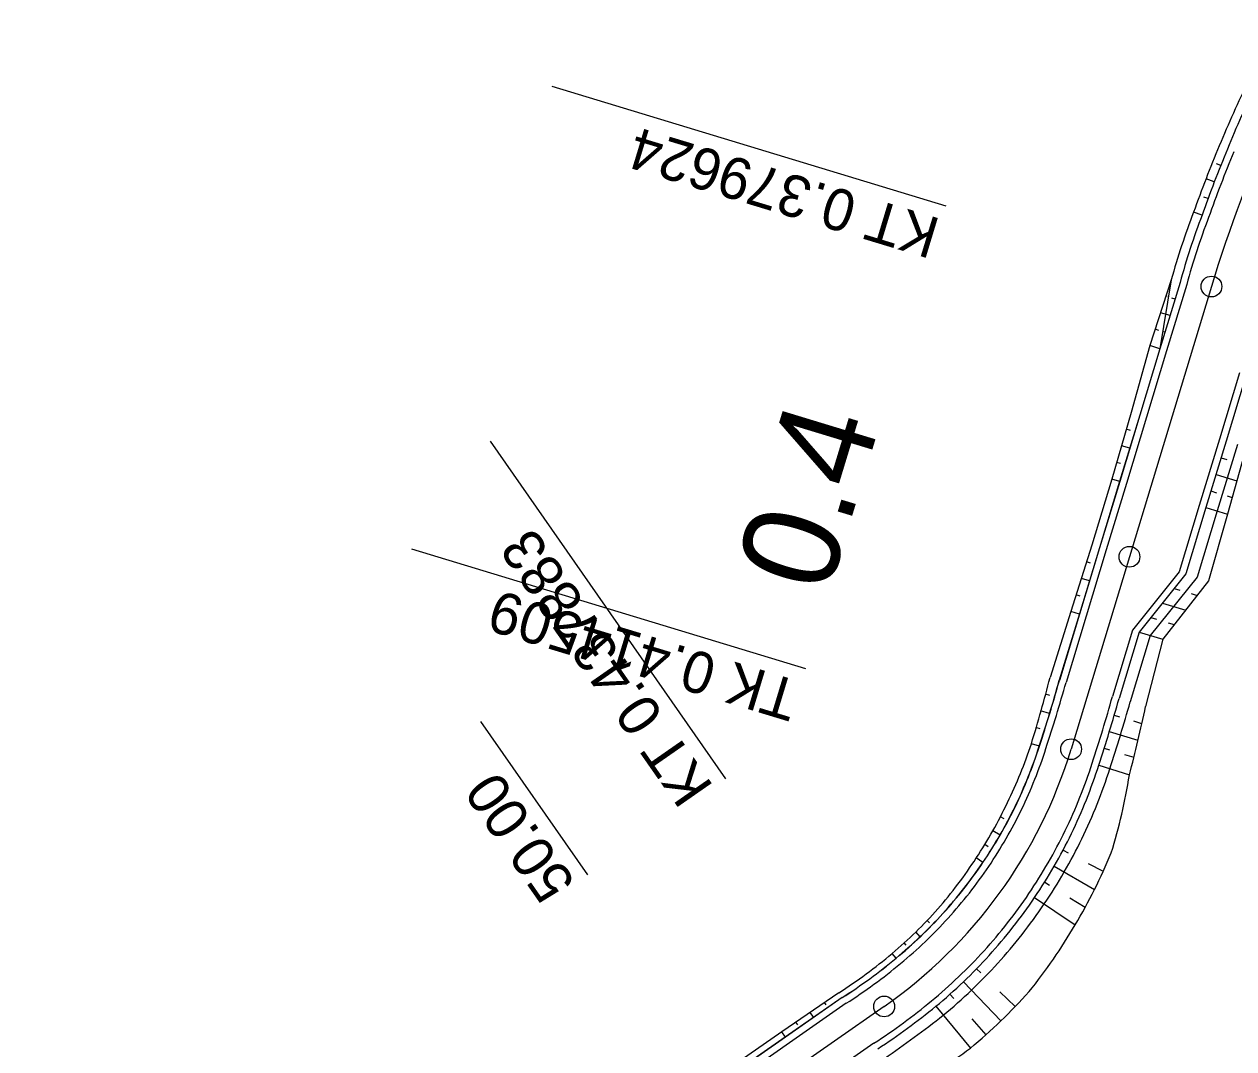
# Model space of a CAD drawing. Extents: x -481656 to -478728, y -1113199 to -1110710.
# Drawn here: x -479662.7 to -479575.4, y -1112765 to -1112691.1 of the extents above; entities that cross this region are included whole.
import ezdxf

# ---------------------------------------------------------------- set-up
doc = ezdxf.new("R2010")
doc.units = 0
for name, color, linetype in [('C1_HATCH_SLOPE_L', 7, 'Continuous'), ('C1_HATCH_SLOPE_R', 7, 'Continuous'), ('C1_HECTOMETRY', 7, 'Continuous'), ('C1_HLBODY', 7, 'Continuous'), ('C1_HRANA_TELESO', 7, 'Continuous'), ('C1_KORUNA', 7, 'Continuous'), ('C1_OSA', 7, 'Continuous'), ('C1_PRIKOP', 7, 'Continuous'), ('C1_STANICENI', 7, 'Continuous'), ('C1_VOZOVKA', 7, 'Continuous'), ('C1_ZPEVKRAJ', 7, 'Continuous')]:
    doc.layers.add(name, color=color, linetype=linetype)

msp = doc.modelspace()

# ---------------------------------------------------------------- linework, layer by layer
at = {"layer": 'C1_HATCH_SLOPE_L'}
for p, q in [((-479576.368, -1112722.337), (-479575.961, -1112722.46)), ((-479576.731, -1112723.533), (-479575.23, -1112723.988)), ((-479577.094, -1112724.729), (-479576.687, -1112724.852)), ((-479575.926, -1112725.084), (-479575.571, -1112725.191)), ((-479577.456, -1112725.925), (-479575.912, -1112726.394)), ((-479579.749, -1112731.761), (-479579.344, -1112731.884)), ((-479580.59, -1112732.812), (-479578.92, -1112733.319)), ((-479578.518, -1112732.134), (-479578.097, -1112732.262)), ((-479581.432, -1112733.863), (-479581.029, -1112733.985)), ((-479580.185, -1112734.241), (-479579.743, -1112734.375)), ((-479582.273, -1112734.914), (-479580.567, -1112735.432)), ((-479584.087, -1112740.895), (-479583.686, -1112741.016)), ((-479582.691, -1112741.318), (-479582.097, -1112741.499)), ((-479584.45, -1112742.092), (-479582.382, -1112742.719)), ((-479584.812, -1112743.288), (-479584.412, -1112743.41)), ((-479583.34, -1112743.734), (-479582.668, -1112743.938)), ((-479585.188, -1112744.513), (-479582.976, -1112745.218)), ((-479587.761, -1112750.637), (-479587.391, -1112750.833)), ((-479588.405, -1112751.802), (-479585.493, -1112753.479)), ((-479585.944, -1112751.6), (-479584.868, -1112752.17)), ((-479589.09, -1112752.942), (-479588.734, -1112753.164)), ((-479589.815, -1112754.057), (-479586.887, -1112756.035)), ((-479587.273, -1112754.078), (-479586.167, -1112754.769)), ((-479594.01, -1112759.208), (-479593.71, -1112759.5)), ((-479594.955, -1112760.144), (-479592.261, -1112762.966)), ((-479592.316, -1112760.86), (-479591.221, -1112761.928)), ((-479595.934, -1112761.045), (-479595.656, -1112761.358)), ((-479596.944, -1112761.911), (-479594.449, -1112764.928)), ((-479594.357, -1112762.818), (-479593.337, -1112763.966))]:
    msp.add_line(p, q, dxfattribs=at)
at = {"layer": 'C1_HATCH_SLOPE_R'}
for p, q in [((-479576.979, -1112701.01), (-479576.979, -1112701.01)), ((-479576.389, -1112701.244), (-479576.684, -1112701.127)), ((-479576.853, -1112702.435), (-479577.45, -1112702.206)), ((-479577.907, -1112703.409), (-479577.907, -1112703.409)), ((-479577.303, -1112703.632), (-479577.605, -1112703.52)), ((-479577.737, -1112704.833), (-479578.349, -1112704.617)), ((-479580.255, -1112710.708), (-479580.347, -1112710.68)), ((-479579.686, -1112710.881), (-479579.924, -1112710.808)), ((-479580.049, -1112712.077), (-479580.736, -1112711.868)), ((-479580.852, -1112713.14), (-479581.126, -1112713.056)), ((-479580.411, -1112713.273), (-479580.494, -1112713.248)), ((-479580.774, -1112714.469), (-479581.516, -1112714.244)), ((-479582.9, -1112720.356), (-479583.203, -1112720.264)), ((-479582.588, -1112720.45), (-479582.593, -1112720.448)), ((-479582.951, -1112721.646), (-479583.551, -1112721.464)), ((-479583.611, -1112722.752), (-479583.899, -1112722.665)), ((-479583.314, -1112722.843), (-479583.318, -1112722.842)), ((-479583.677, -1112724.039), (-479584.246, -1112723.866)), ((-479585.786, -1112729.93), (-479586.072, -1112729.844)), ((-479585.491, -1112730.02), (-479585.496, -1112730.018)), ((-479585.853, -1112731.216), (-479586.447, -1112731.036)), ((-479586.524, -1112732.318), (-479586.823, -1112732.228)), ((-479586.216, -1112732.412), (-479586.221, -1112732.41)), ((-479586.579, -1112733.608), (-479587.198, -1112733.421)), ((-479588.723, -1112739.489), (-479589.043, -1112739.392)), ((-479588.393, -1112739.589), (-479588.398, -1112739.588)), ((-479588.756, -1112740.785), (-479589.382, -1112740.596)), ((-479589.424, -1112741.889), (-479589.721, -1112741.799)), ((-479589.119, -1112741.982), (-479589.124, -1112741.98)), ((-479589.475, -1112743.147), (-479590.051, -1112742.963)), ((-479592.017, -1112748.383), (-479592.287, -1112748.24)), ((-479591.738, -1112748.531), (-479591.742, -1112748.528)), ((-479592.304, -1112749.555), (-479592.832, -1112749.25)), ((-479593.164, -1112750.396), (-479593.413, -1112750.241)), ((-479593.543, -1112751.538), (-479594.029, -1112751.21)), ((-479592.906, -1112750.557), (-479592.91, -1112750.554)), ((-479597.408, -1112755.894), (-479597.577, -1112755.729)), ((-479597.232, -1112756.066), (-479597.236, -1112756.062)), ((-479599.078, -1112757.507), (-479599.227, -1112757.34)), ((-479598.063, -1112756.889), (-479598.387, -1112756.549)), ((-479599.811, -1112758.443), (-479600.094, -1112758.101)), ((-479598.923, -1112757.682), (-479598.926, -1112757.678)), ((-479604.849, -1112761.816), (-479604.971, -1112761.641)), ((-479605.747, -1112762.713), (-479606.002, -1112762.347)), ((-479604.721, -1112761.999), (-479604.724, -1112761.995)), ((-479606.906, -1112763.236), (-479607.034, -1112763.052)), ((-479606.773, -1112763.428), (-479606.776, -1112763.424)), ((-479607.798, -1112764.142), (-479608.066, -1112763.758))]:
    msp.add_line(p, q, dxfattribs=at)
at = {"layer": 'C1_HECTOMETRY'}
msp.add_circle((-479582.975, -1112729.477), 0.75, dxfattribs=at)
at = {"layer": 'C1_HLBODY'}
for p, q in [((-479596.2, -1112704.173), (-479624.621, -1112695.553)), ((-479612.105, -1112745.51), (-479629.082, -1112721.141)), ((-479606.325, -1112737.556), (-479634.746, -1112728.936))]:
    msp.add_line(p, q, dxfattribs=at)
for centre in [(-479577.061, -1112709.978), (-479587.186, -1112743.361), (-479600.673, -1112761.92)]:
    msp.add_circle(centre, 0.75, dxfattribs=at)
at = {"layer": 'C1_HRANA_TELESO'}
for p, q in [((-479579.957, -1112709.492), (-479581.516, -1112714.244)), ((-479581.516, -1112714.244), (-479582.856, -1112719.063)), ((-479582.856, -1112719.063), (-479584.246, -1112723.866)), ((-479574.548, -1112721.583), (-479575.912, -1112726.394)), ((-479584.246, -1112723.866), (-479585.696, -1112728.651)), ((-479575.912, -1112726.394), (-479577.274, -1112731.206)), ((-479585.696, -1112728.651), (-479587.198, -1112733.421)), ((-479577.274, -1112731.206), (-479580.567, -1112735.432)), ((-479587.198, -1112733.421), (-479588.703, -1112738.189)), ((-479580.567, -1112735.432), (-479581.811, -1112740.279)), ((-479603.939, -1112760.935), (-479608.066, -1112763.758)), ((-479608.066, -1112763.758), (-479612.175, -1112766.607))]:
    msp.add_line(p, q, dxfattribs=at)
for centre, radius, start, end in [((-479481.554, -1112739.428), 102.869, 154.48923, 157.35405), ((-479481.495, -1112739.339), 102.889, 157.41238, 160.27719), ((-479530.354, -1112723.151), 51.449, 158.88479, 164.60438), ((-479682.155, -1112714.38), 96.436, 342.75896, 345.70668), ((-479697.913, -1112715.507), 118.715, 345.50664, 347.95577), ((-479620.605, -1112733.017), 32.131, 333.7838, 341.96907), ((-479622.486, -1112738.943), 40.005, 342.69717, 350.97564), ((-479620.843, -1112733.489), 32.141, 326.54035, 334.72589), ((-479621.063, -1112733.701), 32.209, 318.8842, 327.07087), ((-479621.82, -1112735.325), 40.61, 329.33852, 337.53802), ((-479620.942, -1112733.456), 32.28, 310.22869, 318.41433), ((-479622.159, -1112735.21), 40.961, 321.24111, 329.44137), ((-479625.925, -1112727.085), 40.364, 303.00424, 309.78883), ((-479620.807, -1112733.325), 41.152, 309.82966, 318.01484), ((-479632.039, -1112713.382), 63.796, 301.15571, 306.10154)]:
    msp.add_arc(centre, radius, start, end, dxfattribs=at)
at = {"layer": 'C1_KORUNA'}
for p, q in [((-479579.323, -1112709.684), (-479580.774, -1112714.469)), ((-479580.774, -1112714.469), (-479582.225, -1112719.254)), ((-479574.554, -1112716.356), (-479576.005, -1112721.141)), ((-479582.225, -1112719.254), (-479583.677, -1112724.039)), ((-479576.005, -1112721.141), (-479577.456, -1112725.925)), ((-479583.677, -1112724.039), (-479585.128, -1112728.824)), ((-479577.456, -1112725.925), (-479578.908, -1112730.71)), ((-479585.128, -1112728.824), (-479586.579, -1112733.608)), ((-479578.908, -1112730.71), (-479582.273, -1112734.914)), ((-479586.579, -1112733.608), (-479588.03, -1112738.393)), ((-479582.273, -1112734.914), (-479583.724, -1112739.699)), ((-479603.696, -1112761.284), (-479607.798, -1112764.142)), ((-479607.798, -1112764.142), (-479611.901, -1112767.001))]:
    msp.add_line(p, q, dxfattribs=at)
for centre, radius, start, end in [((-479481.366, -1112739.002), 102.25, 154.74832, 157.61311), ((-479481.366, -1112739.002), 102.25, 157.61311, 160.4779), ((-479529.996, -1112723.122), 51.125, 159.03921, 164.76111), ((-479682.725, -1112712.201), 98.25, 341.64128, 344.53899), ((-479691.345, -1112709.601), 111.75, 341.79558, 344.37554), ((-479620.679, -1112733.202), 32.75, 334.13833, 342.32344), ((-479620.679, -1112733.202), 37.25, 334.13833, 342.32344), ((-479620.679, -1112733.202), 32.75, 325.95321, 334.13833), ((-479620.679, -1112733.202), 37.25, 325.95322, 334.13833), ((-479620.679, -1112733.202), 32.75, 317.7681, 325.95321), ((-479620.679, -1112733.202), 37.25, 317.76811, 325.95322), ((-479620.679, -1112733.202), 32.75, 309.58299, 317.7681), ((-479620.679, -1112733.202), 37.25, 309.583, 317.76811), ((-479626.364, -1112726.22), 41.754, 302.88139, 309.48942), ((-479627.852, -1112724.154), 48.794, 303.21491, 309.30428)]:
    msp.add_arc(centre, radius, start, end, dxfattribs=at)
at = {"layer": 'C1_OSA'}
for p, q in [((-479577.061, -1112709.978), (-479587.186, -1112743.361)), ((-479600.673, -1112761.92), (-479662.716, -1112805.144))]:
    msp.add_line(p, q, dxfattribs=at)
for centre, radius, start, end in [((-479481.366, -1112739.002), 100, 147.85753, 163.12732), ((-479620.679, -1112733.202), 35, 304.86324, 343.12729)]:
    msp.add_arc(centre, radius, start, end, dxfattribs=at)
at = {"layer": 'C1_PRIKOP'}
for p, q in [((-479579.957, -1112709.492), (-479580.784, -1112714.466)), ((-479580.784, -1112714.466), (-479582.235, -1112719.251)), ((-479582.235, -1112719.251), (-479583.686, -1112724.036)), ((-479575.191, -1112721.387), (-479576.642, -1112726.172)), ((-479583.686, -1112724.036), (-479585.137, -1112728.821)), ((-479576.642, -1112726.172), (-479578.094, -1112730.957)), ((-479585.137, -1112728.821), (-479586.589, -1112733.605)), ((-479578.094, -1112730.957), (-479581.471, -1112735.157)), ((-479586.589, -1112733.605), (-479588.04, -1112738.39)), ((-479581.471, -1112735.157), (-479582.922, -1112739.942)), ((-479603.701, -1112761.276), (-479607.804, -1112764.134)), ((-479607.804, -1112764.134), (-479611.907, -1112766.992))]:
    msp.add_line(p, q, dxfattribs=at)
for centre, radius, start, end in [((-479682.706, -1112712.207), 98.22, 341.64089, 344.5394), ((-479692.949, -1112709.117), 114.263, 341.82016, 344.34927), ((-479620.679, -1112733.202), 32.74, 334.13833, 342.32344), ((-479620.679, -1112733.202), 38.088, 334.13834, 342.32345), ((-479620.679, -1112733.202), 32.74, 325.95321, 334.13833), ((-479620.679, -1112733.202), 38.088, 325.95323, 334.13834), ((-479620.679, -1112733.202), 32.74, 317.7681, 325.95321), ((-479620.679, -1112733.202), 38.088, 317.76811, 325.95323), ((-479620.679, -1112733.202), 32.74, 309.58299, 317.7681), ((-479623.26, -1112730.462), 36.497, 302.40532, 309.96514), ((-479620.679, -1112733.202), 38.088, 309.583, 317.76811), ((-479653.686, -1112688.945), 93.27, 304.65876, 307.88574)]:
    msp.add_arc(centre, radius, start, end, dxfattribs=at)
at = {"layer": 'C1_STANICENI'}
msp.add_line((-479622.047, -1112752.436), (-479629.764, -1112741.359), dxfattribs=at)
at = {"layer": 'C1_VOZOVKA'}
for p, q in [((-479578.844, -1112709.83), (-479580.296, -1112714.614)), ((-479580.296, -1112714.614), (-479581.747, -1112719.399)), ((-479575.032, -1112716.211), (-479576.484, -1112720.995)), ((-479581.747, -1112719.399), (-479583.198, -1112724.184)), ((-479576.484, -1112720.995), (-479577.935, -1112725.78)), ((-479583.198, -1112724.184), (-479584.649, -1112728.969)), ((-479577.935, -1112725.78), (-479579.386, -1112730.565)), ((-479584.649, -1112728.969), (-479586.101, -1112733.753)), ((-479579.386, -1112730.565), (-479582.751, -1112734.769)), ((-479586.101, -1112733.753), (-479587.552, -1112738.538)), ((-479582.751, -1112734.769), (-479584.203, -1112739.554)), ((-479603.41, -1112761.695), (-479607.512, -1112764.553)), ((-479607.512, -1112764.553), (-479611.615, -1112767.411)), ((-479601.409, -1112764.566), (-479605.512, -1112767.425))]:
    msp.add_line(p, q, dxfattribs=at)
for centre, radius, start, end in [((-479481.366, -1112739.002), 101.75, 157.61311, 160.4779), ((-479529.758, -1112723.201), 50.875, 159.03862, 164.76259), ((-479683.683, -1112711.912), 99.75, 341.66054, 344.5187), ((-479690.387, -1112709.89), 110.25, 341.78035, 344.39177), ((-479620.679, -1112733.202), 33.25, 334.13833, 342.32344), ((-479620.679, -1112733.202), 36.75, 334.13833, 342.32344), ((-479620.679, -1112733.202), 33.25, 325.95321, 334.13833), ((-479620.679, -1112733.202), 36.75, 325.95322, 334.13833), ((-479620.679, -1112733.202), 33.25, 317.7681, 325.95321), ((-479620.679, -1112733.202), 36.75, 317.76811, 325.95322), ((-479620.679, -1112733.202), 33.25, 309.58299, 317.7681), ((-479620.679, -1112733.202), 36.75, 309.583, 317.76811), ((-479625.5, -1112727.396), 40.796, 302.78358, 309.60484), ((-479623.669, -1112729.862), 41.229, 302.67653, 309.82724)]:
    msp.add_arc(centre, radius, start, end, dxfattribs=at)
at = {"layer": 'C1_ZPEVKRAJ'}
for p, q in [((-479578.844, -1112709.83), (-479580.296, -1112714.614)), ((-479580.296, -1112714.614), (-479581.747, -1112719.399)), ((-479575.032, -1112716.211), (-479576.484, -1112720.995)), ((-479581.747, -1112719.399), (-479583.198, -1112724.184)), ((-479576.484, -1112720.995), (-479577.935, -1112725.78)), ((-479583.198, -1112724.184), (-479584.649, -1112728.969)), ((-479577.935, -1112725.78), (-479579.386, -1112730.565)), ((-479584.649, -1112728.969), (-479586.101, -1112733.753)), ((-479579.386, -1112730.565), (-479582.751, -1112734.769)), ((-479586.101, -1112733.753), (-479587.552, -1112738.538)), ((-479582.751, -1112734.769), (-479584.203, -1112739.554)), ((-479603.41, -1112761.695), (-479607.512, -1112764.553)), ((-479607.512, -1112764.553), (-479611.615, -1112767.411)), ((-479601.409, -1112764.566), (-479605.512, -1112767.425))]:
    msp.add_line(p, q, dxfattribs=at)
for centre, radius, start, end in [((-479481.366, -1112739.002), 101.75, 157.61311, 160.4779), ((-479529.758, -1112723.201), 50.875, 159.03862, 164.76259), ((-479683.683, -1112711.912), 99.75, 341.66054, 344.5187), ((-479690.387, -1112709.89), 110.25, 341.78035, 344.39177), ((-479620.679, -1112733.202), 33.25, 334.13833, 342.32344), ((-479620.679, -1112733.202), 36.75, 334.13833, 342.32344), ((-479620.679, -1112733.202), 33.25, 325.95321, 334.13833), ((-479620.679, -1112733.202), 36.75, 325.95322, 334.13833), ((-479620.679, -1112733.202), 33.25, 317.7681, 325.95321), ((-479620.679, -1112733.202), 36.75, 317.76811, 325.95322), ((-479620.679, -1112733.202), 33.25, 309.58299, 317.7681), ((-479620.679, -1112733.202), 36.75, 309.583, 317.76811), ((-479625.5, -1112727.396), 40.796, 302.78358, 309.60484), ((-479623.669, -1112729.862), 41.229, 302.67653, 309.82724)]:
    msp.add_arc(centre, radius, start, end, dxfattribs=at)

# ---------------------------------------------------------------- texts
at = {"layer": 'C1_HECTOMETRY'}
msp.add_text('0.4', height=6.999, rotation=73.08168, dxfattribs=at).set_placement((-479604.744, -1112732.32))
at = {"layer": 'C1_HLBODY'}
for s, height, rotation, p in [('KT 0.379624', 2.999, 163.1273, (-479596.489, -1112705.13)), ('KT 0.437883', 3, 124.86326, (-479612.925, -1112746.082)), ('TK 0.414509', 2.999, 163.1273, (-479606.614, -1112738.513))]:
    msp.add_text(s, height=height, rotation=rotation, dxfattribs=at).set_placement(p)
at = {"layer": 'C1_STANICENI'}
msp.add_text('50.00', height=3, rotation=124.86326, dxfattribs=at).set_placement((-479622.867, -1112753.009))

doc.saveas('drawing.dxf')
